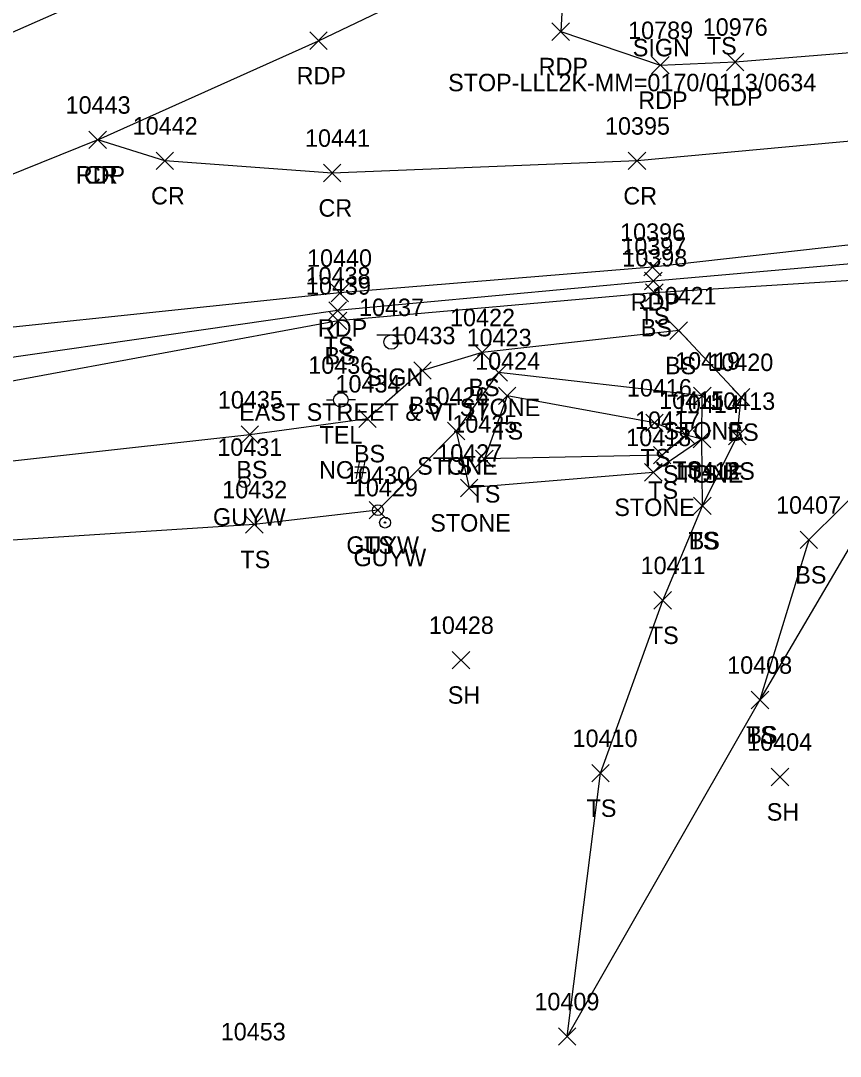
# Model space of a CAD drawing. Extents: x 1475671 to 1477951, y 592661 to 593821.
# Drawn here: x 1476484.8 to 1476578.6, y 592957 to 593075.6 of the extents above; entities that cross this region are included whole.
import ezdxf

# ---------------------------------------------------------------- set-up
doc = ezdxf.new("R2010")
doc.units = 0
for name, color, linetype in [('L_A', 7, 'Continuous'), ('L_I', 7, 'Continuous'), ('L_TIC', 7, 'Continuous'), ('LASF', 7, 'Continuous'), ('LELB', 7, 'Continuous'), ('P_A', 7, 'Continuous'), ('P_I', 7, 'Continuous'), ('P_TIC', 7, 'Continuous'), ('PET', 7, 'Continuous'), ('PRC', 7, 'Continuous'), ('S_A', 7, 'Continuous'), ('S_C', 7, 'Continuous'), ('S_I', 7, 'Continuous'), ('SSGN', 7, 'Continuous'), ('U_A', 7, 'Continuous'), ('U_C', 7, 'Continuous'), ('U_I', 7, 'Continuous'), ('UP', 7, 'Continuous'), ('UPGW', 7, 'Continuous')]:
    doc.layers.add(name, color=color, linetype=linetype)

msp = doc.modelspace()

# ---------------------------------------------------------------- linework, layer by layer
at = {"layer": 'L_TIC'}
for points in [[(1476556.23, 593044.74), (1476558.23, 593046.74)], [(1476558.23, 593044.74), (1476556.23, 593046.74)], [(1476556.34, 593043.4), (1476558.34, 593045.4)], [(1476558.34, 593043.4), (1476556.34, 593045.4)], [(1476520.08, 593041.35), (1476522.08, 593043.35)], [(1476522.08, 593041.35), (1476520.08, 593043.35)], [(1476520.14, 593040.18), (1476522.14, 593042.18)], [(1476522.14, 593040.18), (1476520.14, 593042.18)], [(1476559.13, 593039.06), (1476561.13, 593041.06)], [(1476561.13, 593039.06), (1476559.13, 593041.06)], [(1476536.62, 593036.56), (1476538.62, 593038.56)], [(1476538.62, 593036.56), (1476536.62, 593038.56)], [(1476529.79, 593034.5), (1476531.79, 593036.5)], [(1476531.79, 593034.5), (1476529.79, 593036.5)], [(1476538.51, 593034.27), (1476540.51, 593036.27)], [(1476540.51, 593034.27), (1476538.51, 593036.27)], [(1476539.5, 593031.58), (1476541.5, 593033.58)], [(1476541.5, 593031.58), (1476539.5, 593033.58)], [(1476561.83, 593031.59), (1476563.83, 593033.59)], [(1476563.83, 593031.59), (1476561.83, 593033.59)], [(1476566.28, 593031.43), (1476568.28, 593033.43)], [(1476568.28, 593031.43), (1476566.28, 593033.43)], [(1476523.51, 593028.97), (1476525.51, 593030.97)], [(1476525.51, 593028.97), (1476523.51, 593030.97)], [(1476556.36, 593028.51), (1476558.36, 593030.51)], [(1476558.36, 593028.51), (1476556.36, 593030.51)], [(1476510.04, 593027.14), (1476512.04, 593029.14)], [(1476512.04, 593027.14), (1476510.04, 593029.14)], [(1476533.65, 593027.56), (1476535.65, 593029.56)], [(1476535.65, 593027.56), (1476533.65, 593029.56)], [(1476533.65, 593027.56), (1476535.65, 593029.56)], [(1476535.65, 593027.56), (1476533.65, 593029.56)], [(1476559.99, 593027.09), (1476561.99, 593029.09)], [(1476561.99, 593027.09), (1476559.99, 593029.09)], [(1476559.99, 593027.09), (1476561.99, 593029.09)], [(1476561.99, 593027.09), (1476559.99, 593029.09)], [(1476565.84, 593026.98), (1476567.84, 593028.98)], [(1476567.84, 593026.98), (1476565.84, 593028.98)], [(1476561.79, 593026.64), (1476563.79, 593028.64)], [(1476563.79, 593026.64), (1476561.79, 593028.64)], [(1476561.79, 593026.64), (1476563.79, 593028.64)], [(1476563.79, 593026.64), (1476561.79, 593028.64)], [(1476561.79, 593026.64), (1476563.79, 593028.64)], [(1476563.79, 593026.64), (1476561.79, 593028.64)], [(1476557.23, 593024.8), (1476559.23, 593026.8)], [(1476559.23, 593024.8), (1476557.23, 593026.8)], [(1476536.88, 593024.37), (1476538.88, 593026.37)], [(1476538.88, 593024.37), (1476536.88, 593026.37)], [(1476536.88, 593024.37), (1476538.88, 593026.37)], [(1476538.88, 593024.37), (1476536.88, 593026.37)], [(1476556.22, 593022.83), (1476558.22, 593024.83)], [(1476558.22, 593022.83), (1476556.22, 593024.83)], [(1476535.15, 593021.04), (1476537.15, 593023.04)], [(1476537.15, 593021.04), (1476535.15, 593023.04)], [(1476535.15, 593021.04), (1476537.15, 593023.04)], [(1476537.15, 593021.04), (1476535.15, 593023.04)], [(1476524.69, 593018.5), (1476526.69, 593020.5)], [(1476526.69, 593018.5), (1476524.69, 593020.5)], [(1476561.84, 593019), (1476563.84, 593021)], [(1476563.84, 593019), (1476561.84, 593021)], [(1476561.84, 593019), (1476563.84, 593021)], [(1476563.84, 593019), (1476561.84, 593021)], [(1476510.54, 593016.85), (1476512.54, 593018.85)], [(1476512.54, 593016.85), (1476510.54, 593018.85)], [(1476574.03, 593015.09), (1476576.03, 593017.09)], [(1476576.03, 593015.09), (1476574.03, 593017.09)], [(1476557.3, 593008.17), (1476559.3, 593010.17)], [(1476559.3, 593008.17), (1476557.3, 593010.17)], [(1476534.2, 593001.33), (1476536.2, 593003.33)], [(1476536.2, 593001.33), (1476534.2, 593003.33)], [(1476568.43, 592996.76), (1476570.43, 592998.76)], [(1476570.43, 592996.76), (1476568.43, 592998.76)], [(1476568.43, 592996.76), (1476570.43, 592998.76)], [(1476570.43, 592996.76), (1476568.43, 592998.76)], [(1476550.17, 592988.37), (1476552.17, 592990.37)], [(1476552.17, 592988.37), (1476550.17, 592990.37)], [(1476570.72, 592987.94), (1476572.72, 592989.94)], [(1476572.72, 592987.94), (1476570.72, 592989.94)], [(1476546.37, 592958.22), (1476548.37, 592960.22)], [(1476548.37, 592958.22), (1476546.37, 592960.22)], [(1476546.37, 592958.22), (1476548.37, 592960.22)], [(1476548.37, 592958.22), (1476546.37, 592960.22)]]:
    msp.add_lwpolyline(points, dxfattribs=at)
at = {"layer": 'LASF'}
for points in [[(1476562.79, 593027.64), (1476562.83, 593032.59), (1476539.51, 593035.27), (1476534.65, 593028.56), (1476536.15, 593022.04)], [(1476562.79, 593027.64), (1476557.22, 593023.83), (1476536.15, 593022.04)]]:
    msp.add_lwpolyline(points, dxfattribs=at)
at = {"layer": 'LELB'}
for points in [[(1476841.85, 593018.32), (1476825.12, 593035.12), (1476811.51, 593051.32), (1476779.42, 593062.14), (1476752.49, 593064.9), (1476722.37, 593064.49), (1476691.91, 593057.79), (1476666.49, 593052.08), (1476661.25, 593053.21), (1476656.95, 593052.9), (1476655.98, 593055.35), (1476654.36, 593057.56), (1476652.4, 593057.3), (1476651.11, 593057.01), (1476646.46, 593054.41), (1476629, 593052.03), (1476594.01, 593046.66), (1476557.34, 593044.4), (1476521.14, 593041.18), (1476464.22, 593030.64)], [(1476656.72, 593061.12), (1476648.18, 593059.88), (1476630.02, 593056.59), (1476594.66, 593048.99), (1476557.23, 593045.74), (1476521.08, 593042.35), (1476462.84, 593033.95), (1476419.94, 593027.86), (1476367.81, 593018.54), (1476319.05, 593010.3), (1476266.9, 593001.04), (1476164.01, 592984.31)], [(1476839.39, 593010.15), (1476820.84, 593030.96), (1476810.95, 593047.74), (1476779.57, 593058.62), (1476752.41, 593061.01), (1476722.8, 593061.3), (1476693.96, 593054.33), (1476667.9, 593046.42), (1476659.43, 593048.7), (1476654.11, 593050.55), (1476650.93, 593054.11), (1476646.9, 593052.35), (1476629.79, 593048.23), (1476596.33, 593042), (1476591.8, 593026.06), (1476582.27, 593023.28), (1476575.03, 593016.09), (1476569.43, 592997.76), (1476547.37, 592959.22)], [(1476646.9, 593052.35), (1476629.3, 593045.84), (1476598.68, 593038.97), (1476596.35, 593024.58), (1476582.59, 593020.19), (1476569.43, 592997.76)], [(1476562.84, 593020), (1476566.84, 593027.98), (1476567.28, 593032.43), (1476560.13, 593040.06), (1476537.62, 593037.56), (1476530.79, 593035.5), (1476524.51, 593029.97), (1476511.04, 593028.14), (1476465.56, 593023.07)], [(1476547.37, 592959.22), (1476551.17, 592989.37), (1476558.3, 593009.17), (1476562.84, 593020), (1476562.79, 593027.64), (1476560.99, 593028.09), (1476557.36, 593029.51), (1476540.5, 593032.58), (1476537.88, 593025.37)], [(1476534.65, 593028.56), (1476525.69, 593019.5), (1476511.54, 593017.85), (1476467.31, 593015.01), (1476422.73, 593008.46), (1476366.85, 593001.28), (1476356.63, 592997.77), (1476347.04, 593000.45), (1476320.8, 592997.35), (1476267.98, 592990.13), (1476216.9, 592984.46), (1476165.76, 592976.73), (1476117.9, 592968.73), (1476100.74, 592966.91), (1476051.72, 592958.25), (1475996.01, 592950.36), (1475948.39, 592939), (1475900.82, 592931.75), (1475857.92, 592923.91), (1475803.59, 592912.34), (1475790.59, 592904.71)], [(1476560.99, 593028.09), (1476558.23, 593025.8), (1476537.88, 593025.37)]]:
    msp.add_lwpolyline(points, dxfattribs=at)
at = {"layer": 'P_TIC'}
for points in [[(1476545.62, 593073.3), (1476547.62, 593075.3)], [(1476547.62, 593073.3), (1476545.62, 593075.3)], [(1476517.9, 593072.26), (1476519.9, 593074.26)], [(1476519.9, 593072.26), (1476517.9, 593074.26)], [(1476557.02, 593069.45), (1476559.02, 593071.45)], [(1476559.02, 593069.45), (1476557.02, 593071.45)], [(1476565.6, 593069.83), (1476567.6, 593071.83)], [(1476567.6, 593069.83), (1476565.6, 593071.83)], [(1476492.61, 593060.9), (1476494.61, 593062.9)], [(1476494.61, 593060.9), (1476492.61, 593062.9)], [(1476492.61, 593060.9), (1476494.61, 593062.9)], [(1476494.61, 593060.9), (1476492.61, 593062.9)], [(1476492.61, 593060.9), (1476494.61, 593062.9)], [(1476494.61, 593060.9), (1476492.61, 593062.9)], [(1476500.29, 593058.51), (1476502.29, 593060.51)], [(1476502.29, 593058.51), (1476500.29, 593060.51)], [(1476554.36, 593058.5), (1476556.36, 593060.5)], [(1476556.36, 593058.5), (1476554.36, 593060.5)], [(1476519.45, 593057.11), (1476521.45, 593059.11)], [(1476521.45, 593057.11), (1476519.45, 593059.11)], [(1476556.14, 593046.34), (1476558.14, 593048.34)], [(1476558.14, 593046.34), (1476556.14, 593048.34)], [(1476520.33, 593043.37), (1476522.33, 593045.37)], [(1476522.33, 593043.37), (1476520.33, 593045.37)]]:
    msp.add_lwpolyline(points, dxfattribs=at)
at = {"layer": 'PET'}
for points in [[(1476493.61, 593061.9), (1476518.9, 593073.26), (1476550.12, 593088.22), (1476579.1, 593105.35), (1476612.57, 593127.79), (1476627.64, 593138.01), (1476653.65, 593155.86), (1476677.37, 593174.62), (1476705.43, 593196.67), (1476722.66, 593210.69), (1476749.61, 593233.45), (1476768.81, 593249.96), (1476797.5, 593274.02), (1476824.82, 593297.55), (1476845, 593315.29), (1476868.19, 593333.86), (1476888.66, 593352.98), (1476918.01, 593376.95), (1476944.23, 593398.87), (1476967.73, 593418.7), (1476998.53, 593444.47)], [(1476550.12, 593088.22), (1476546.99, 593080.79), (1476546.62, 593074.3), (1476558.02, 593070.45), (1476566.6, 593070.83), (1476605.7, 593074.02), (1476651.65, 593078.89), (1476683.81, 593086.28), (1476716.78, 593091.72), (1476756.3, 593096.32), (1476786.76, 593094.61), (1476795.52, 593092.66), (1476816.88, 593085.29), (1476835.43, 593074.22), (1476828.62, 593102.02), (1476824.42, 593119.75), (1476821.59, 593140.77), (1476821.02, 593163.56), (1476821.92, 593180.44), (1476827.12, 593207.84), (1476837.47, 593243.39), (1476848.83, 593278.3), (1476858.44, 593303.19), (1476868.19, 593333.86)], [(1476876.69, 592931.37), (1476866.39, 592975.94), (1476855.42, 593012.87), (1476851.35, 593023.14), (1476844.63, 593035.78), (1476834.27, 593048.7), (1476823.42, 593058.99), (1476807.6, 593067.92), (1476802.87, 593070.05), (1476785.81, 593074.83), (1476762.31, 593077.35), (1476735.17, 593076.04), (1476692.75, 593070.03), (1476654.27, 593063.28), (1476593.38, 593051.4), (1476557.14, 593047.34), (1476521.33, 593044.37), (1476462.5, 593038.2)], [(1476493.61, 593061.9), (1476461.35, 593048.89), (1476408.69, 593032.05)]]:
    msp.add_lwpolyline(points, dxfattribs=at)
at = {"layer": 'PRC'}
for points in [[(1476461.98, 593064.62), (1476520.7, 593090.52), (1476540.79, 593101.34), (1476577.67, 593121.61), (1476614.51, 593145.69), (1476649.36, 593170.81), (1476687.02, 593200.01), (1476716.69, 593224.25), (1476733.58, 593238.31), (1476760.9, 593261.21), (1476795.35, 593290.14), (1476823.06, 593313.51), (1476854.07, 593339.52), (1476875.7, 593357.51), (1476907.01, 593384.08), (1476934.06, 593407.68), (1476963.46, 593432.81)], [(1476783.7, 593084.94), (1476761.58, 593086.67), (1476734.11, 593084.66), (1476691.9, 593077.87), (1476653.54, 593071.49), (1476592.22, 593062.91), (1476555.36, 593059.5), (1476520.45, 593058.11), (1476501.29, 593059.51), (1476493.61, 593061.9)]]:
    msp.add_lwpolyline(points, dxfattribs=at)
at = {"layer": 'SSGN'}
for p, q in [((1476525.57, 593039.59), (1476528.9, 593039.59)), ((1476527.22, 593038.75), (1476527.22, 593038.75))]:
    msp.add_line(p, q, dxfattribs=at)
msp.add_circle((1476527.22, 593038.75), 0.833, dxfattribs=at)
at = {"layer": 'UP'}
for p, q in [((1476519.79, 593032.12), (1476520.61, 593032.12)), ((1476521.45, 593032.12), (1476521.45, 593032.12)), ((1476523.11, 593032.12), (1476522.28, 593032.12)), ((1476522.28, 593032.12), (1476522.28, 593032.12)), ((1476523.11, 593032.12), (1476523.11, 593032.12))]:
    msp.add_line(p, q, dxfattribs=at)
msp.add_circle((1476521.45, 593032.12), 0.833, dxfattribs=at)
at = {"layer": 'UPGW'}
for centre, radius in [((1476510.41, 593022.72), 0.625), ((1476510.41, 593022.72), 0.0833), ((1476525.69, 593019.5), 0.625), ((1476525.69, 593019.5), 0.0833), ((1476526.51, 593018.08), 0.625), ((1476526.51, 593018.08), 0.0833)]:
    msp.add_circle(centre, radius, dxfattribs=at)

# ---------------------------------------------------------------- texts
at = {"layer": 'L_A'}
for s, p in [('TS', (1476563.35, 593071.68)), ('TS', (1476555.64, 593040.74)), ('BS', (1476555.78, 593039.4)), ('TS', (1476519.49, 593037.35)), ('BS', (1476519.58, 593036.18)), ('BS', (1476558.57, 593035.06)), ('BS', (1476536.06, 593032.56)), ('BS', (1476529.24, 593030.5)), ('STONE', (1476535.06, 593030.27)), ('TS', (1476538.91, 593027.58)), ('STONE', (1476558.38, 593027.59)), ('BS', (1476565.72, 593027.43)), ('BS', (1476522.95, 593024.97)), ('TS', (1476555.77, 593024.51)), ('STONE', (1476530.19, 593023.56)), ('TS', (1476533.05, 593023.56)), ('BS', (1476509.48, 593023.14)), ('STONE', (1476558.33, 593022.64)), ('STONE', (1476558.33, 593022.64)), ('TS', (1476559.4, 593023.09)), ('TS', (1476559.4, 593023.09)), ('TS', (1476561.2, 593022.64)), ('BS', (1476565.28, 593022.98)), ('TS', (1476556.64, 593020.8)), ('TS', (1476536.29, 593020.37)), ('TS', (1476536.29, 593020.37)), ('STONE', (1476552.76, 593018.83)), ('STONE', (1476531.69, 593017.04)), ('STONE', (1476531.69, 593017.04)), ('TS', (1476561.25, 593015)), ('BS', (1476561.28, 593015)), ('TS', (1476524.1, 593014.5)), ('TS', (1476509.95, 593012.85)), ('BS', (1476573.47, 593011.09)), ('TS', (1476556.71, 593004.17)), ('SH', (1476533.69, 592997.33)), ('TS', (1476567.84, 592992.76)), ('BS', (1476567.87, 592992.76)), ('TS', (1476549.58, 592984.37)), ('SH', (1476570.21, 592983.94))]:
    msp.add_text(s, height=2, dxfattribs=at).set_placement(p)
at = {"layer": 'L_I'}
for s, p in [('10397', (1476553.56, 593048.74)), ('10398', (1476553.67, 593047.4)), ('10438', (1476517.41, 593045.35)), ('10439', (1476517.46, 593044.18)), ('10421', (1476557.03, 593043.06)), ('10422', (1476533.95, 593040.56)), ('10433', (1476527.13, 593038.5)), ('10423', (1476535.85, 593038.27)), ('10424', (1476536.83, 593035.58)), ('10419', (1476559.72, 593035.59)), ('10420', (1476563.52, 593035.43)), ('10434', (1476520.84, 593032.97)), ('10426', (1476530.92, 593031.56)), ('10426', (1476530.92, 593031.56)), ('10416', (1476554.2, 593032.51)), ('10435', (1476507.37, 593031.14)), ('10415', (1476557.89, 593031.09)), ('10415', (1476557.89, 593031.09)), ('10414', (1476559.69, 593030.64)), ('10414', (1476559.69, 593030.64)), ('10414', (1476559.69, 593030.64)), ('10413', (1476563.74, 593030.98)), ('10425', (1476534.21, 593028.37)), ('10425', (1476534.21, 593028.37)), ('10417', (1476555.13, 593028.8)), ('10418', (1476554.12, 593026.83)), ('10427', (1476532.48, 593025.04)), ('10427', (1476532.48, 593025.04)), ('10430', (1476521.93, 593022.5)), ('10412', (1476559.74, 593023)), ('10412', (1476559.74, 593023)), ('10432', (1476507.87, 593020.85)), ('10407', (1476571.28, 593019.09)), ('10411', (1476555.77, 593012.17)), ('10428', (1476531.53, 593005.33)), ('10408', (1476565.68, 593000.76)), ('10408', (1476565.68, 593000.76)), ('10410', (1476547.98, 592992.37)), ('10404', (1476567.97, 592991.94)), ('10409', (1476543.61, 592962.22)), ('10409', (1476543.61, 592962.22)), ('10453', (1476507.7, 592958.78))]:
    msp.add_text(s, height=2, dxfattribs=at).set_placement(p)
at = {"layer": 'P_A'}
for s, p in [('RDP', (1476516.39, 593068.26)), ('RDP', (1476544.1, 593069.3)), ('RDP', (1476555.5, 593065.45)), ('RDP', (1476564.09, 593065.83)), ('RDP', (1476491.1, 593056.9)), ('RDP', (1476491.1, 593056.9)), ('CR', (1476492.04, 593056.9)), ('CR', (1476499.72, 593054.51)), ('CR', (1476553.79, 593054.5)), ('CR', (1476518.89, 593053.11)), ('RDP', (1476554.63, 593042.34)), ('RDP', (1476518.82, 593039.37))]:
    msp.add_text(s, height=2, dxfattribs=at).set_placement(p)
at = {"layer": 'P_I'}
for s, p in [('10789', (1476554.34, 593073.45)), ('10976', (1476562.88, 593073.83)), ('10443', (1476489.94, 593064.9)), ('10443', (1476489.94, 593064.9)), ('10443', (1476489.94, 593064.9)), ('10442', (1476497.62, 593062.51)), ('10395', (1476551.69, 593062.5)), ('10441', (1476517.35, 593061.11)), ('10396', (1476553.42, 593050.34)), ('10440', (1476517.58, 593047.37))]:
    msp.add_text(s, height=2, dxfattribs=at).set_placement(p)
at = {"layer": 'S_A'}
for p in [(1476554.87, 593071.47), (1476524.36, 593033.73)]:
    msp.add_text('SIGN', height=2, dxfattribs=at).set_placement(p)
at = {"layer": 'S_C'}
for s, p in [('STOP-LLL2K-MM=0170/0113/0634', (1476533.73, 593067.47)), ('EAST STREET & VT 17', (1476509.81, 593029.73))]:
    msp.add_text(s, height=2, dxfattribs=at).set_placement(p)
at = {"layer": 'S_I'}
msp.add_text('10437', height=2, dxfattribs=at).set_placement((1476523.53, 593041.73))
at = {"layer": 'U_A'}
for s, p in [('TEL', (1476519.01, 593027.12)), ('GUYW', (1476506.81, 593017.72)), ('GUYW', (1476522.08, 593014.5)), ('GUYW', (1476522.9, 593013.08))]:
    msp.add_text(s, height=2, dxfattribs=at).set_placement(p)
at = {"layer": 'U_C'}
msp.add_text('NO#', height=2, dxfattribs=at).set_placement((1476518.96, 593023.12))
at = {"layer": 'U_I'}
for s, p in [('10436', (1476517.72, 593035.12)), ('10431', (1476507.31, 593025.72)), ('10430', (1476521.93, 593022.5)), ('10429', (1476522.83, 593021.08))]:
    msp.add_text(s, height=2, dxfattribs=at).set_placement(p)

doc.saveas('drawing.dxf')
